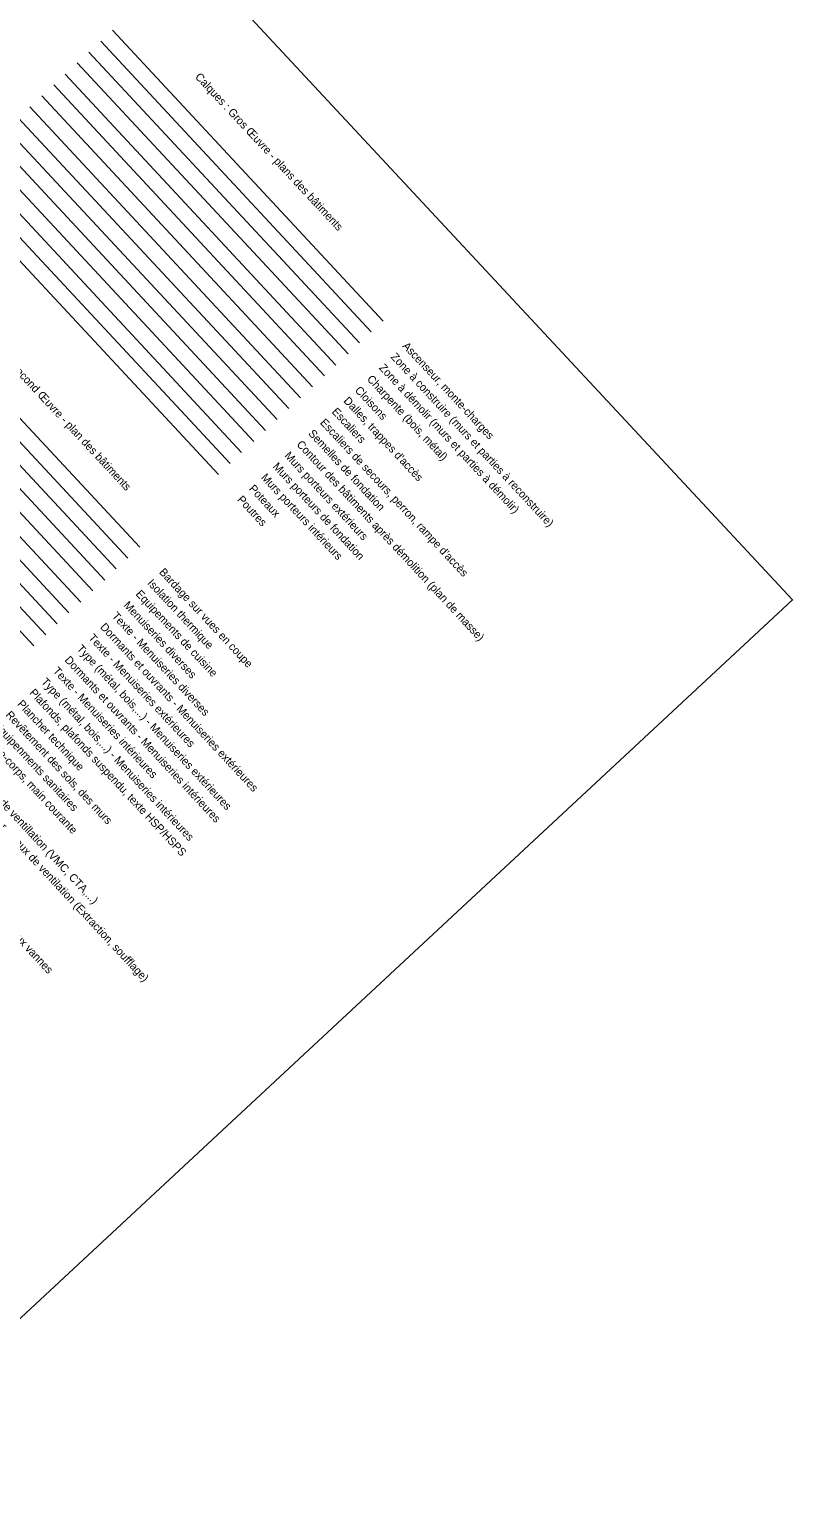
# Model space of a CAD drawing. Extents: x 704383 to 706615, y 7057567 to 7059313.
# Drawn here: x 706567 to 706614.7, y 7057612.8 to 7057704.4 of the extents above; entities that cross this region are included whole.
import ezdxf

# ---------------------------------------------------------------- set-up
doc = ezdxf.new("R2010")
doc.units = 0
for name, color, linetype in [('DH_CADRE -CARTOUCHE', 7, 'Continuous'), ('GO_A CONSTRUIRE', 7, 'Continuous'), ('GO_A DEMOLIR', 7, 'Continuous'), ('GO_ASCENSEUR', 7, 'Continuous'), ('GO_BATIMENT_DEMOLI', 7, 'Continuous'), ('GO_CHARPENTE', 7, 'Continuous'), ('GO_CLOISON', 7, 'Continuous'), ('GO_DALLE', 7, 'Continuous'), ('GO_ESCALIER_EXTERIEUR', 7, 'Continuous'), ('GO_ESCALIER_INTERIEUR', 7, 'Continuous'), ('GO_FONDATION', 7, 'Continuous'), ('GO_MUR_EXTERIEUR', 7, 'Continuous'), ('GO_MUR_FONDATION', 7, 'Continuous'), ('GO_MUR_INTERIEUR', 7, 'Continuous'), ('GO_POTEAU', 7, 'Continuous'), ('GO_POUTRE', 7, 'Continuous'), ('SO_BARDAGE', 7, 'Continuous'), ('SO_EQUIP_CUISINE', 7, 'Continuous'), ('SO_EU_EV_LIAISON', 7, 'Continuous'), ('SO_GARDE_CORPS', 7, 'Continuous'), ('SO_ISOLATION', 7, 'Continuous'), ('SO_MENUISERIE DIVERS_EQUIP', 7, 'Continuous'), ('SO_MENUISERIE DIVERS_TEXTE', 7, 'Continuous'), ('SO_MENUISERIE EXT_ EQUIP', 7, 'Continuous'), ('SO_MENUISERIE EXT_TEXTE', 7, 'Continuous'), ('SO_MENUISERIE EXT_TYPE', 7, 'Continuous'), ('SO_MENUISERIE INT_ EQUIP', 7, 'Continuous'), ('SO_MENUISERIE INT_TEXTE', 7, 'Continuous'), ('SO_MENUISERIE INT_TYPE', 7, 'Continuous'), ('SO_PLAFOND', 7, 'Continuous'), ('SO_PLANCHER TECHNIQUE', 7, 'Continuous'), ('SO_REVETEMENT_SOL_MUR', 7, 'Continuous'), ('SO_SANITAIRE', 7, 'Continuous'), ('SO_VMC_CVC_CTA_EQUIP', 7, 'Continuous'), ('SO_VMC_CVC_CTA_RES-TEXTE', 7, 'Continuous')]:
    doc.layers.add(name, color=color, linetype=linetype)

msp = doc.modelspace()

# ---------------------------------------------------------------- linework, layer by layer
at = {"layer": 'DH_CADRE -CARTOUCHE'}
msp.add_lwpolyline([(706573.792, 7057712.707), (706614.66, 7057668.778), (706534.124, 7057593.852), (706493.255, 7057637.781)], close=True, dxfattribs=at)
at = {"layer": 'GO_A CONSTRUIRE'}
msp.add_line((706571.444, 7057703.694), (706588.347, 7057685.526), dxfattribs=at)
at = {"layer": 'GO_A DEMOLIR'}
msp.add_line((706570.712, 7057703.013), (706587.615, 7057684.845), dxfattribs=at)
at = {"layer": 'GO_ASCENSEUR'}
msp.add_line((706572.177, 7057704.375), (706589.079, 7057686.207), dxfattribs=at)
at = {"layer": 'GO_BATIMENT_DEMOLI'}
msp.add_line((706565.565, 7057698.224), (706582.467, 7057680.056), dxfattribs=at)
at = {"layer": 'GO_CHARPENTE'}
msp.add_line((706569.98, 7057702.332), (706586.893, 7057684.153), dxfattribs=at)
at = {"layer": 'GO_CLOISON'}
msp.add_line((706569.225, 7057701.629), (706586.138, 7057683.451), dxfattribs=at)
at = {"layer": 'GO_DALLE'}
msp.add_line((706568.516, 7057700.969), (706585.428, 7057682.791), dxfattribs=at)
at = {"layer": 'GO_ESCALIER_EXTERIEUR'}
msp.add_line((706567.029, 7057699.586), (706583.931, 7057681.418), dxfattribs=at)
at = {"layer": 'GO_ESCALIER_INTERIEUR'}
msp.add_line((706567.761, 7057700.267), (706584.663, 7057682.099), dxfattribs=at)
at = {"layer": 'GO_FONDATION'}
msp.add_line((706566.297, 7057698.905), (706583.199, 7057680.737), dxfattribs=at)
at = {"layer": 'GO_MUR_EXTERIEUR'}
msp.add_line((706564.832, 7057697.543), (706581.745, 7057679.364), dxfattribs=at)
at = {"layer": 'GO_MUR_FONDATION'}
msp.add_line((706564.1, 7057696.861), (706581.013, 7057678.683), dxfattribs=at)
at = {"layer": 'GO_MUR_INTERIEUR'}
msp.add_line((706563.345, 7057696.159), (706580.248, 7057677.991), dxfattribs=at)
at = {"layer": 'GO_POTEAU'}
msp.add_line((706562.613, 7057695.478), (706579.526, 7057677.299), dxfattribs=at)
at = {"layer": 'GO_POUTRE'}
msp.add_line((706561.881, 7057694.797), (706578.794, 7057676.618), dxfattribs=at)
at = {"layer": 'SO_BARDAGE'}
msp.add_line((706556.978, 7057690.246), (706573.881, 7057672.077), dxfattribs=at)
at = {"layer": 'SO_EQUIP_CUISINE'}
msp.add_line((706555.514, 7057688.883), (706572.416, 7057670.715), dxfattribs=at)
at = {"layer": 'SO_ISOLATION'}
msp.add_line((706556.246, 7057689.564), (706573.148, 7057671.396), dxfattribs=at)
at = {"layer": 'SO_MENUISERIE DIVERS_EQUIP'}
msp.add_line((706554.782, 7057688.202), (706571.694, 7057670.023), dxfattribs=at)
at = {"layer": 'SO_MENUISERIE DIVERS_TEXTE'}
msp.add_line((706554.05, 7057687.521), (706570.962, 7057669.342), dxfattribs=at)
at = {"layer": 'SO_MENUISERIE EXT_ EQUIP'}
msp.add_line((706553.295, 7057686.819), (706570.197, 7057668.651), dxfattribs=at)
at = {"layer": 'SO_MENUISERIE EXT_TEXTE'}
msp.add_line((706552.563, 7057686.138), (706569.465, 7057667.969), dxfattribs=at)
at = {"layer": 'SO_MENUISERIE EXT_TYPE'}
msp.add_line((706551.83, 7057685.456), (706568.733, 7057667.288), dxfattribs=at)
at = {"layer": 'SO_MENUISERIE INT_ EQUIP'}
msp.add_line((706551.098, 7057684.775), (706568.011, 7057666.596), dxfattribs=at)
at = {"layer": 'SO_MENUISERIE INT_TEXTE'}
msp.add_line((706550.366, 7057684.094), (706567.279, 7057665.915), dxfattribs=at)

# ---------------------------------------------------------------- texts
at = {"layer": 'DH_CADRE -CARTOUCHE'}
for s, p in [(' Calques : Gros Œuvre - plans des bâtiments', (706577.179, 7057701.567)), (' Calques et styles des traits : Second Œuvre - plan des bâtiments', (706559.839, 7057689.74))]:
    msp.add_text(s, height=0.5, rotation=312.93319, dxfattribs=at).set_placement(p)
at = {"layer": 'GO_A CONSTRUIRE'}
msp.add_text('Zone à construire (murs et parties à reconstruire)', height=0.5, rotation=312.93319, dxfattribs=at).set_placement((706589.527, 7057683.936))
at = {"layer": 'GO_A DEMOLIR'}
msp.add_text('Zone à démolir (murs et parties à démolir)', height=0.5, rotation=312.93319, dxfattribs=at).set_placement((706588.795, 7057683.255))
at = {"layer": 'GO_ASCENSEUR'}
msp.add_text('Ascenseur, monte-charges', height=0.5, rotation=312.93319, dxfattribs=at).set_placement((706590.259, 7057684.617))
at = {"layer": 'GO_BATIMENT_DEMOLI'}
msp.add_text('Contour des bâtiments après démolition (plan de masse)', height=0.5, rotation=312.93319, dxfattribs=at).set_placement((706583.647, 7057678.466))
at = {"layer": 'GO_CHARPENTE'}
msp.add_text('Charpente (bois, métal)', height=0.5, rotation=312.93319, dxfattribs=at).set_placement((706588.04, 7057682.552))
at = {"layer": 'GO_CLOISON'}
msp.add_text('Cloisons', height=0.5, rotation=312.93319, dxfattribs=at).set_placement((706587.285, 7057681.85))
at = {"layer": 'GO_DALLE'}
msp.add_text("Dalles, trappes d'accès", height=0.5, rotation=312.93319, dxfattribs=at).set_placement((706586.576, 7057681.19))
at = {"layer": 'GO_ESCALIER_EXTERIEUR'}
msp.add_text("Escaliers de secours, perron, rampe d'accès", height=0.5, rotation=312.93319, dxfattribs=at).set_placement((706585.112, 7057679.828))
at = {"layer": 'GO_ESCALIER_INTERIEUR'}
msp.add_text('Escaliers', height=0.5, rotation=312.93319, dxfattribs=at).set_placement((706585.844, 7057680.509))
at = {"layer": 'GO_FONDATION'}
msp.add_text('Semelles de fondation', height=0.5, rotation=312.93319, dxfattribs=at).set_placement((706584.379, 7057679.147))
at = {"layer": 'GO_MUR_EXTERIEUR'}
msp.add_text('Murs porteurs extérieurs', height=0.5, rotation=312.93319, dxfattribs=at).set_placement((706582.892, 7057677.763))
at = {"layer": 'GO_MUR_FONDATION'}
msp.add_text('Murs porteurs de fondation', height=0.5, rotation=312.93319, dxfattribs=at).set_placement((706582.16, 7057677.082))
at = {"layer": 'GO_MUR_INTERIEUR'}
msp.add_text('Murs porteurs intérieurs', height=0.5, rotation=312.93319, dxfattribs=at).set_placement((706581.428, 7057676.401))
at = {"layer": 'GO_POTEAU'}
msp.add_text('Poteaux', height=0.5, rotation=312.93319, dxfattribs=at).set_placement((706580.673, 7057675.699))
at = {"layer": 'GO_POUTRE'}
msp.add_text('Poutres', height=0.5, rotation=312.93319, dxfattribs=at).set_placement((706579.941, 7057675.018))
at = {"layer": 'SO_BARDAGE'}
msp.add_text('Bardage sur vues en coupe', height=0.5, rotation=312.93319, dxfattribs=at).set_placement((706575.061, 7057670.487))
at = {"layer": 'SO_EQUIP_CUISINE'}
msp.add_text('Equipements de cuisine', height=0.5, rotation=312.93319, dxfattribs=at).set_placement((706573.597, 7057669.125))
at = {"layer": 'SO_EU_EV_LIAISON'}
msp.add_text('Liaison - Réseaux eaux usées et eaux vannes', height=0.5, rotation=312.93319, dxfattribs=at).set_placement((706558.84, 7057655.397))
at = {"layer": 'SO_GARDE_CORPS'}
msp.add_text('Garde-corps, main courante', height=0.5, rotation=312.93319, dxfattribs=at).set_placement((706564.01, 7057660.207))
at = {"layer": 'SO_ISOLATION'}
msp.add_text('Isolation thermique', height=0.5, rotation=312.93319, dxfattribs=at).set_placement((706574.329, 7057669.806))
at = {"layer": 'SO_MENUISERIE DIVERS_EQUIP'}
msp.add_text('Menuiseries diverses', height=0.5, rotation=312.93319, dxfattribs=at).set_placement((706572.842, 7057668.423))
at = {"layer": 'SO_MENUISERIE DIVERS_TEXTE'}
msp.add_text('Texte - Menuiseries diverses', height=0.5, rotation=312.93319, dxfattribs=at).set_placement((706572.11, 7057667.742))
at = {"layer": 'SO_MENUISERIE EXT_ EQUIP'}
msp.add_text('Dormants et ouvrants - Menuiseries extérieures', height=0.5, rotation=312.93319, dxfattribs=at).set_placement((706571.377, 7057667.06))
at = {"layer": 'SO_MENUISERIE EXT_TEXTE'}
msp.add_text('Texte - Menuiseries extérieures', height=0.5, rotation=312.93319, dxfattribs=at).set_placement((706570.645, 7057666.379))
at = {"layer": 'SO_MENUISERIE EXT_TYPE'}
msp.add_text('Type (métal, bois,...) - Menuiseries extérieures', height=0.5, rotation=312.93319, dxfattribs=at).set_placement((706569.913, 7057665.698))
at = {"layer": 'SO_MENUISERIE INT_ EQUIP'}
msp.add_text('Dormants et ouvrants - Menuiseries intérieures', height=0.5, rotation=312.93319, dxfattribs=at).set_placement((706569.158, 7057664.996))
at = {"layer": 'SO_MENUISERIE INT_TEXTE'}
msp.add_text('Texte - Menuiseries intérieures', height=0.5, rotation=312.93319, dxfattribs=at).set_placement((706568.426, 7057664.315))
at = {"layer": 'SO_MENUISERIE INT_TYPE'}
msp.add_text('Type (métal, bois,...) - Menuiseries intérieures', height=0.5, rotation=312.93319, dxfattribs=at).set_placement((706567.694, 7057663.634))
at = {"layer": 'SO_PLAFOND'}
msp.add_text('Plafonds, plafonds suspendu, texte HSP/HSPS', height=0.5, rotation=312.93319, dxfattribs=at).set_placement((706566.962, 7057662.952))
at = {"layer": 'SO_PLANCHER TECHNIQUE'}
msp.add_text('Plancher technique', height=0.5, rotation=312.93319, dxfattribs=at).set_placement((706566.207, 7057662.25))
at = {"layer": 'SO_REVETEMENT_SOL_MUR'}
msp.add_text('Revêtement des sols, des murs', height=0.5, rotation=312.93319, dxfattribs=at).set_placement((706565.475, 7057661.569))
at = {"layer": 'SO_SANITAIRE'}
msp.add_text('Equipenments sanitaires', height=0.5, rotation=312.93319, dxfattribs=at).set_placement((706564.743, 7057660.888))
at = {"layer": 'SO_VMC_CVC_CTA_EQUIP'}
msp.add_text('Equipement de ventillation (VMC, CTA,...)', height=0.5, rotation=312.93319, dxfattribs=at).set_placement((706562.523, 7057658.823))
at = {"layer": 'SO_VMC_CVC_CTA_RES-TEXTE'}
msp.add_text('Liaison + texte - réseaux de ventilation (Extraction, soufflage)', height=0.5, rotation=312.93319, dxfattribs=at).set_placement((706561.791, 7057658.142))

doc.saveas('drawing.dxf')
